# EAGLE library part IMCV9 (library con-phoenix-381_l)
Invertierter Mini-Combicon 3.81mm vertikal 9-polig IMCV 1,5/9-G-3,81 (ohne Gegenstecker)
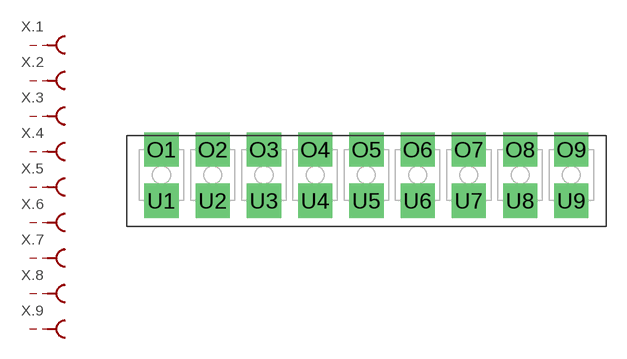
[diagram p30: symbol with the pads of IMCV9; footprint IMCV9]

Designator prefix X; gates .5=MCBU .4=MCBU .3=MCBU .2=MCBU .1=MCBU .6=MCBU .7=MCBU .8=MCBU .9=MCBU

## IMCV9  [IMCV9]
O1  .1:S  pas
O2  .2:S  pas
O3  .3:S  pas
O4  .4:S  pas
O5  .5:S  pas
O6  .6:S  pas
O7  .7:S  pas
O8  .8:S  pas
O9  .9:S  pas
U1  .1:SK  pas
U2  .2:SK  pas
U3  .3:SK  pas
U4  .4:SK  pas
U5  .5:SK  pas
U6  .6:SK  pas
U7  .7:SK  pas
U8  .8:SK  pas
U9  .9:SK  pas

## Footprint IMCV9 (pad centres in mm)
Mini-Combicon 3.81mm vertical 9-polig invertiert (ohne Gegenstecker)
drill 1.3 pad 2.54 square: O1 -15.24,1.905; O2 -11.43,1.905; O3 -7.62,1.905; O4 -3.81,1.905; O5 0,1.905; O6 3.81,1.905; O7 7.62,1.905; O8 11.43,1.905; O9 15.24,1.905; U1 -15.24,-1.905; U2 -11.43,-1.905; U3 -7.62,-1.905; U4 -3.81,-1.905; U5 0,-1.905; U6 3.81,-1.905; U7 7.62,-1.905; U8 11.43,-1.905; U9 15.24,-1.905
